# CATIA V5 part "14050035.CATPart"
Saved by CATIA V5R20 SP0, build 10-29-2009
Part number: 14050035
Definition: NONE
Nomenclature: 14050035
Source: Unknown
Description: 14050035
Bounding box of the stored display mesh (mm): x -17.5 to 70, y -39 to 29.1, z -29.1 to 29.1
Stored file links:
  C:\Users\Utente\Desktop\IO LAVORO\3D X SITO CF\X SITO\PLASTICA\RF2\14050035.CATPart
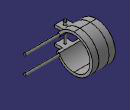
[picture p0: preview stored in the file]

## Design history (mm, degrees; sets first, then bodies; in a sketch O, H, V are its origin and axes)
Body1 "14050035" (main body)
  Solid1: solid without history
